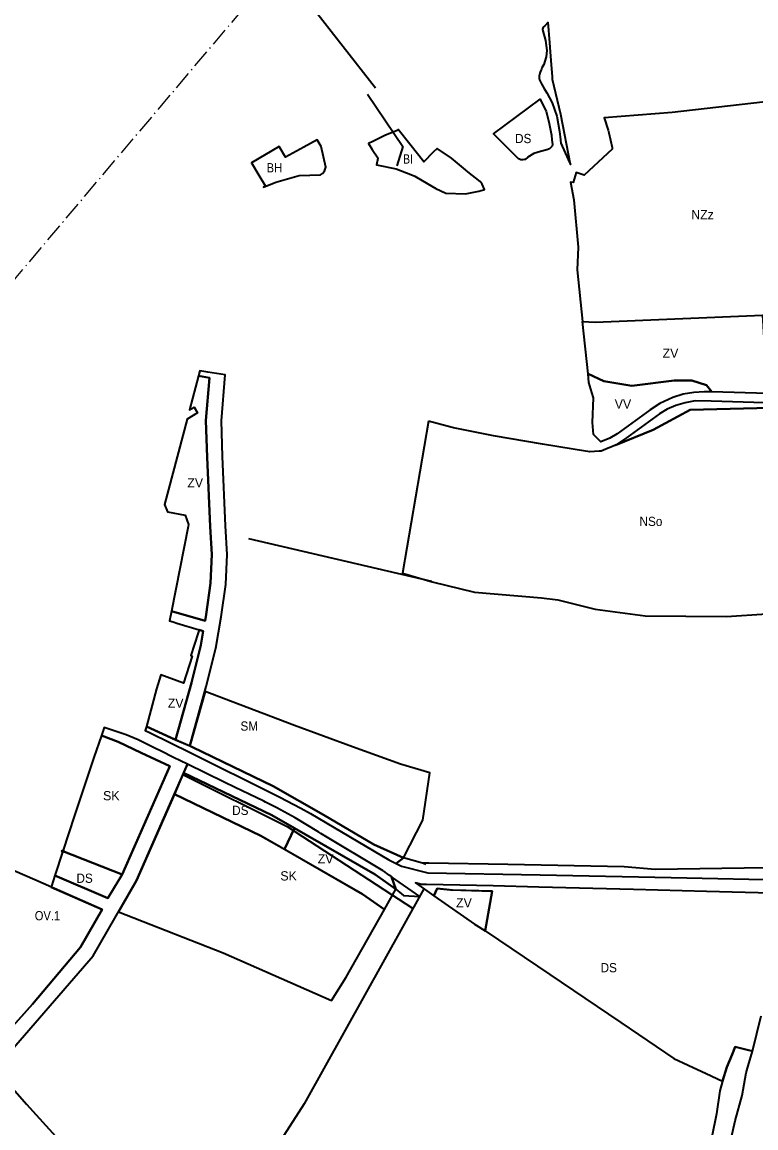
# Model space of a CAD drawing. Extents: x -650276 to -642489, y -1074311 to -1066658.
# Drawn here: x -646170 to -645218, y -1071706 to -1070271 of the extents above; entities that cross this region are included whole.
import ezdxf

# ---------------------------------------------------------------- set-up
doc = ezdxf.new("R2010")
doc.units = 0
doc.header["$LTSCALE"] = 4.8
doc.header["$PDMODE"] = 32
doc.header["$PDSIZE"] = 2.4
doc.linetypes.add('DOT_DASHED', pattern=[7.7, 5, -1.2, 0.3, -1.2])
for name, color, linetype, lineweight in [('1', 7, 'Continuous', 35), ('11', 7, 'Continuous', 35), ('15', 7, 'Continuous', 35), ('18', 7, 'Continuous', 35), ('2', 7, 'Continuous', 35), ('20', 7, 'Continuous', 35), ('24', 7, 'Continuous', 35), ('40', 7, 'Continuous', 35), ('45', 7, 'Continuous', 35), ('46', 7, 'Continuous', 35), ('54', 7, 'Continuous', 35), ('55', 7, 'Continuous', 53), ('56', 7, 'Continuous', 35)]:
    doc.layers.add(name, color=color, linetype=linetype, lineweight=lineweight)
doc.layers.add('62', color=7, linetype='Continuous')
doc.layers.add('63', color=7, linetype='Continuous')

msp = doc.modelspace()

# ---------------------------------------------------------------- linework, layer by layer
at = {"layer": '1'}
msp.add_lwpolyline([(-645862.66, -1070469.5), (-645853.98, -1070483.81), (-645856.87, -1070485.24), (-645840.59, -1070479), (-645810.44, -1070470.17), (-645782.57, -1070469.22), (-645780.38, -1070467.64), (-645777.8, -1070464.4), (-645776.04, -1070459.38), (-645782.13, -1070432.59), (-645786.9, -1070423.81), (-645804.58, -1070433.53), (-645828.24, -1070446.54), (-645836.32, -1070432.55), (-645872.35, -1070453.55)], close=True, dxfattribs=at)
at = {"layer": '11'}
msp.add_lwpolyline([(-646066.165, -1071422.155), (-646153.5, -1071383.85), (-646208.577, -1071360.044), (-646241.68, -1071416.887), (-646258.487, -1071439.265), (-646275.615, -1071460.886), (-646289.976, -1071477.514), (-646330.914, -1071521.11), (-646324, -1071535), (-646217.978, -1071613.552), (-646211.407, -1071606.247), (-646156.471, -1071545.166), (-646094.063, -1071471.007)], close=True, dxfattribs=at)
at = {"layer": '15'}
for points in [[(-645487.361, -1070271.37), (-645491.94, -1070275.85), (-645491.94, -1070275.85), (-645493.8, -1070277.67), (-645494.57, -1070280.34), (-645494.12, -1070282.52), (-645490.79, -1070294.93), (-645489.31, -1070307.77), (-645490.03, -1070316.27), (-645493.05, -1070326.11), (-645495.44, -1070330.67), (-645496.12, -1070332.34), (-645497.83, -1070336.16), (-645498.75, -1070338.98), (-645499.01, -1070340.96), (-645499.09, -1070343.91), (-645498.74, -1070345.87), (-645498, -1070347.74), (-645496.02, -1070351.15), (-645491.97, -1070358.14), (-645488.99, -1070362.96)], [(-645487.361, -1070271.37), (-645491.94, -1070275.85), (-645491.94, -1070275.85), (-645493.8, -1070277.67), (-645494.57, -1070280.34), (-645494.12, -1070282.52), (-645490.79, -1070294.93), (-645489.31, -1070307.77), (-645490.03, -1070316.27), (-645493.05, -1070326.11), (-645495.44, -1070330.67), (-645496.12, -1070332.34), (-645497.83, -1070336.16), (-645498.75, -1070338.98), (-645499.01, -1070340.96), (-645499.09, -1070343.91), (-645498.74, -1070345.87), (-645498, -1070347.74), (-645496.02, -1070351.15), (-645491.97, -1070358.14)], [(-645458.32, -1070455.91), (-645471, -1070391), (-645481.67, -1070345.39), (-645481.65, -1070342.07), (-645483.34, -1070321.17), (-645484.27, -1070309.7), (-645485.21, -1070298.03), (-645487.361, -1070271.37)], [(-645483.34, -1070321.17), (-645484.27, -1070309.7), (-645485.21, -1070298.03), (-645487.361, -1070271.37)], [(-645482.16, -1070375.96), (-645476.12, -1070393.13), (-645472.61, -1070413.13), (-645471.87, -1070419.96), (-645470.99, -1070428.07), (-645461.32, -1070449.31), (-645458.32, -1070455.91), (-645471, -1070391), (-645481.67, -1070345.39), (-645481.65, -1070342.07), (-645483.34, -1070321.17)], [(-645491.97, -1070358.14), (-645488.99, -1070362.96), (-645482.16, -1070375.96)], [(-645488.99, -1070362.96), (-645482.16, -1070375.96), (-645476.12, -1070393.13), (-645472.61, -1070413.13), (-645471.87, -1070419.96), (-645470.99, -1070428.07), (-645461.32, -1070449.31), (-645458.32, -1070455.91)], [(-646197.398, -1071620.579), (-646077.593, -1071482.499), (-646021.674, -1071384.575), (-645964.396, -1071254.314), (-645955.342, -1071233.725), (-645973.324, -1071224.925), (-645989.7, -1071216.91), (-645997.62, -1071213.03), (-646019.41, -1071202.36), (-646035.06, -1071195.87), (-646063.59, -1071186.33), (-646067.097, -1071196.699), (-646045.462, -1071204.917), (-646015.387, -1071218.854), (-645978.403, -1071236.481), (-646040.084, -1071376.813), (-646058.719, -1071407.796), (-646127.301, -1071378.036), (-646131.79, -1071391.83), (-646132.229, -1071393.179), (-646066.165, -1071422.155), (-646094.063, -1071471.007), (-646156.471, -1071545.166), (-646211.407, -1071606.247)], [(-645701.44, -1071372.25), (-645782.32, -1071323.5), (-645784.92, -1071321.93), (-645815.65, -1071303.41), (-645839.37, -1071290.6), (-645854.1, -1071282.93), (-645856.26, -1071281.91), (-645875.48, -1071272.81), (-645893.41, -1071264.04), (-645907.62, -1071257.08), (-645955.342, -1071233.725), (-645960.34, -1071245.09), (-645846, -1071300), (-645712, -1071377), (-645712, -1071377)], [(-645712, -1071377), (-645685.098, -1071395.824), (-645690.677, -1071379.721)]]:
    msp.add_lwpolyline(points, dxfattribs=at)
for points in [[(-645911.345, -1070788.463), (-645906.373, -1070728.716), (-645929.077, -1070725.068), (-645939.27, -1070723.43), (-645940.955, -1070729.799), (-645926.784, -1070732.812), (-645931.369, -1070787.913), (-645930.036, -1070835.367), (-645926.084, -1070925.481), (-645923.919, -1070961.855), (-645925.626, -1070998.754), (-645931.24, -1071039.686), (-645932.635, -1071047.688), (-645976.17, -1071035.39), (-645978.58, -1071047.68), (-645973.77, -1071049.17), (-645968.97, -1071050.66), (-645940.25, -1071059.59), (-645934.978, -1071061.119), (-645938.15, -1071079.311), (-645950.283, -1071128.057), (-645970.966, -1071202.169), (-645952.419, -1071210.117), (-645930.943, -1071133.161), (-645918.57, -1071083.449), (-645911.474, -1071042.764), (-645905.69, -1071000.578), (-645903.891, -1070961.723), (-645906.11, -1070924.449), (-645910.048, -1070834.649)], [(-645694.15, -1071357.83), (-645684.785, -1071362.539), (-645674.947, -1071355.071), (-645713.428, -1071337.765), (-645778.69, -1071299.362), (-645844.079, -1071262.487), (-645948.761, -1071211.885), (-645967, -1071204), (-646008.714, -1071184.746), (-646010.14, -1071190.08), (-646004.65, -1071192.55), (-645951.118, -1071219.11), (-645843.45, -1071272.53), (-645835.76, -1071276.35), (-645808.13, -1071290.78), (-645795.97, -1071297.93), (-645694.15, -1071357.83)]]:
    msp.add_lwpolyline(points, close=True, dxfattribs=at)
msp.add_arc((-645538.107, -1071148.434), 277.076, 233.87926, 236.5888, dxfattribs=at)
at = {"layer": '18'}
for points in [[(-645926.81, -1071141.595), (-645932.502, -1071139.426), (-645952.419, -1071210.117), (-645948.761, -1071211.885)], [(-645678.86, -1071233.58), (-645741.09, -1071211.36), (-645816.47, -1071183.63), (-645926.81, -1071141.595)], [(-645948.761, -1071211.885), (-645844.079, -1071262.487), (-645778.69, -1071299.362), (-645713.428, -1071337.765), (-645674.947, -1071355.071)], [(-645674.947, -1071355.071), (-645650.09, -1071306.433), (-645640.737, -1071244.963), (-645678.86, -1071233.58)]]:
    msp.add_lwpolyline(points, dxfattribs=at)
at = {"layer": '2'}
msp.add_lwpolyline([(-645594.769, -1070494.065), (-645577.47, -1070490.3), (-645571.13, -1070488.89), (-645569.97, -1070488.3), (-645572.86, -1070481.41), (-645575.7, -1070477.77), (-645591.49, -1070465.19), (-645594.62, -1070462.7), (-645612.77, -1070447.82), (-645631.63, -1070435.3), (-645636.42, -1070439.93), (-645648.9, -1070452.38), (-645666.99, -1070429.58), (-645682.02, -1070410.65), (-645683.52, -1070411.71), (-645699.33, -1070418.25), (-645714.74, -1070425.84), (-645720.48, -1070428.75), (-645715.56, -1070436.27), (-645708.28, -1070447.28), (-645708.42, -1070447.94), (-645710.14, -1070456.31), (-645684.78, -1070461.52), (-645665.6, -1070469.04), (-645660.29, -1070471.12), (-645643.4, -1070481.02), (-645633.35, -1070486.91), (-645620.22, -1070493)], close=True, dxfattribs=at)
at = {"layer": '20'}
for points in [[(-645990.48, -1071263.958), (-645978.403, -1071236.481), (-646015.387, -1071218.854), (-646045.462, -1071204.917), (-646067.097, -1071196.699), (-646076.713, -1071225.138)], [(-646076.713, -1071225.138), (-646098.66, -1071290.03), (-646102.011, -1071300.326), (-646117.031, -1071346.48)], [(-646117.031, -1071346.48), (-646040.084, -1071376.813), (-645990.48, -1071263.958)]]:
    msp.add_lwpolyline(points, dxfattribs=at)
msp.add_lwpolyline([(-645699.825, -1071422.134), (-645728.105, -1071402.346), (-645859.986, -1071326.563), (-645972.422, -1071272.568), (-646021.674, -1071384.575), (-646044.948, -1071425.333), (-645909.13, -1071478.56), (-645768.62, -1071540.17), (-645749.631, -1071509.908)], close=True, dxfattribs=at)
msp.add_point((-646117.031, -1071346.48), dxfattribs=at)
at = {"layer": '24'}
for points in [[(-645497.81, -1070370.93), (-645497.81, -1070370.93), (-645490.19, -1070386.97), (-645486.54, -1070400.38), (-645483.29, -1070417.99), (-645482.62, -1070423.93), (-645481.93, -1070430.04), (-645482.18, -1070432.13), (-645485.67, -1070435.7), (-645489.34, -1070437.05), (-645497.33, -1070438.82), (-645505.88, -1070441.74), (-645513.81, -1070446.24), (-645517.44, -1070449.23), (-645517.95, -1070449.45), (-645520.4, -1070449.87), (-645521.41, -1070449.84), (-645522.95, -1070449.61), (-645524.42, -1070449.16), (-645525.75, -1070448.41), (-645527.34, -1070447.1), (-645558.36, -1070416.1)], [(-645829.706, -1071343.963), (-645816.714, -1071316.828), (-645846, -1071300), (-645960.34, -1071245.09), (-645972.422, -1071272.568), (-645859.986, -1071326.563)], [(-646045.393, -1071385.64), (-646040.084, -1071376.813), (-646117.031, -1071346.48), (-646127.301, -1071378.036), (-646058.719, -1071407.796)], [(-645675.177, -1071403.922), (-645675.177, -1071403.922), (-645653.742, -1071405.36), (-645690.677, -1071379.721), (-645685.098, -1071395.824)]]:
    msp.add_lwpolyline(points, close=True, dxfattribs=at)
for points in [[(-645179.18, -1070765.86), (-645275.8, -1070762.66), (-645296.51, -1070762.52), (-645309.78, -1070764.88), (-645321.9, -1070768.47), (-645333.12, -1070773.33), (-645342.94, -1070779.31), (-645385.99, -1070810.35), (-645400.05, -1070819.84), (-645351, -1070800), (-645303, -1070774), (-645182, -1070771)], [(-645176.14, -1071277.26), (-645204.341, -1071368.19), (-645348.55, -1071370.559), (-645388.619, -1071366.991), (-645539.738, -1071364.092), (-645642.431, -1071362.259), (-645650.28, -1071362.07), (-645674.947, -1071355.071), (-645684.785, -1071362.539), (-645677.58, -1071366.16), (-645643.56, -1071374.75), (-645497.84, -1071377.53), (-645327.76, -1071380.76), (-645166.34, -1071384.07)], [(-645164.76, -1071401.79), (-645281.92, -1071398.82), (-645376.87, -1071396.41), (-645499.65, -1071393.3), (-645558.9, -1071391.8), (-645645.368, -1071389.96), (-645651.93, -1071389.82), (-645659.6, -1071387.71), (-645647.727, -1071396.036), (-645635.795, -1071404.403), (-645631.44, -1071394.9), (-645614.201, -1071396.844), (-645560.11, -1071398.7), (-645569.07, -1071449.88), (-645501.37, -1071495.68), (-645393.34, -1071568.75), (-645324.17, -1071615.53), (-645324.17, -1071615.53), (-645305.78, -1071624.13), (-645282.54, -1071634.997), (-645261.094, -1071645.025), (-645255.662, -1071626.67), (-645248.786, -1071610.383), (-645244.81, -1071600.61), (-645222.48, -1071606.08), (-645222.48, -1071606.08), (-645211.27, -1071560.01)], [(-645222.48, -1071606.08), (-645244.81, -1071600.61), (-645248.786, -1071610.383), (-645255.662, -1071626.67)], [(-645222.48, -1071606.08), (-645244.81, -1071600.61), (-645248.786, -1071610.383), (-645255.662, -1071626.67)], [(-645339.904, -1072462.677), (-645347.551, -1072443.527), (-645347.677, -1072391.355), (-645346.62, -1072330.914), (-645343.458, -1072278.998), (-645339.908, -1072235.158), (-645335.367, -1072185.207), (-645325.498, -1072102.789), (-645309.01, -1071998.147), (-645285.617, -1071875.733), (-645244.798, -1071696.585), (-645235.793, -1071663.703), (-645230.436, -1071634.261), (-645227.905, -1071625.277), (-645222.48, -1071606.08)], [(-645339.904, -1072462.677), (-645347.551, -1072443.527), (-645347.677, -1072391.355), (-645346.62, -1072330.914), (-645343.458, -1072278.998), (-645339.908, -1072235.158), (-645335.367, -1072185.207), (-645325.498, -1072102.789), (-645309.01, -1071998.147), (-645285.617, -1071875.733), (-645244.798, -1071696.585), (-645235.793, -1071663.703), (-645230.436, -1071634.261), (-645227.905, -1071625.277), (-645222.48, -1071606.08)], [(-645255.662, -1071626.67), (-645261.094, -1071645.025), (-645264.841, -1071657.687), (-645269.077, -1071687.396), (-645274.868, -1071717.176), (-645286.175, -1071761.228), (-645300.076, -1071820.179), (-645313.153, -1071883.081), (-645326.343, -1071952.807)], [(-645255.662, -1071626.67), (-645261.094, -1071645.025), (-645264.841, -1071657.687), (-645269.077, -1071687.396), (-645274.868, -1071717.176), (-645286.175, -1071761.228), (-645300.076, -1071820.179), (-645313.153, -1071883.081)]]:
    msp.add_lwpolyline(points, dxfattribs=at)
at = {"layer": '40'}
for points in [[(-645442.836, -1070659.455), (-645426.34, -1070660.33), (-645209.41, -1070651.2), (-645206.7, -1070694.76), (-645204.66, -1070718.51), (-645203.13, -1070749.36), (-645202.96, -1070752.89), (-645275.236, -1070750.954), (-645282, -1070742), (-645301, -1070736), (-645324, -1070736), (-645379, -1070743), (-645415, -1070737), (-645435.711, -1070727.497)], [(-645932.635, -1071047.688), (-645931.24, -1071039.686), (-645925.626, -1070998.754), (-645923.919, -1070961.855), (-645926.084, -1070925.481), (-645930.036, -1070835.367), (-645931.369, -1070787.913), (-645926.784, -1070732.812), (-645940.955, -1070729.799), (-645952.65, -1070773.98), (-645946.81, -1070770.47), (-645942.3, -1070777.96), (-645955.86, -1070786.21), (-645980.01, -1070877.28), (-645985.28, -1070897.13), (-645981.48, -1070906.35), (-645958.21, -1070910.84), (-645954.01, -1070922.8), (-645954.492, -1070925.251), (-645976.17, -1071035.39)], [(-645970.966, -1071202.169), (-645950.283, -1071128.057), (-645938.15, -1071079.311), (-645934.978, -1071061.119), (-645940.25, -1071059.59), (-645941.45, -1071063.3), (-645950.96, -1071092.8), (-645949.21, -1071093.62), (-645960.66, -1071128.71), (-645990.14, -1071117.76), (-645995.74, -1071136.22), (-646008.714, -1071184.746)], [(-645712, -1071377), (-645816.714, -1071316.828), (-645829.706, -1071343.963), (-645728.105, -1071402.346), (-645699.825, -1071422.134), (-645685.098, -1071395.824)], [(-645583.18, -1071441.3), (-645580.947, -1071442.658), (-645569.07, -1071449.88), (-645560.11, -1071398.7), (-645611.58, -1071397.14), (-645631.44, -1071394.9), (-645635.795, -1071404.403)]]:
    msp.add_lwpolyline(points, close=True, dxfattribs=at)
at = {"layer": '45'}
msp.add_lwpolyline([(-645275.236, -1070750.954), (-645285.11, -1070750.69), (-645298.41, -1070751.48), (-645312.2, -1070753.77), (-645325.82, -1070757.94), (-645342.41, -1070765.76), (-645354.98, -1070774.28), (-645398.04, -1070805.44), (-645407.37, -1070810.95), (-645419.18, -1070815.44), (-645424.969, -1070809.563), (-645428.39, -1070806.09), (-645430, -1070790.68), (-645428.73, -1070758.67), (-645430.84, -1070751.43), (-645434.53, -1070738.77), (-645435.711, -1070727.497), (-645415, -1070737), (-645379, -1070743), (-645324, -1070736), (-645301, -1070736), (-645282, -1070742)], close=True, dxfattribs=at)
at = {"layer": '46'}
for points in [[(-645023.048, -1070595.033), (-645014.277, -1070543.11), (-645004.327, -1070461.264), (-645001.312, -1070412.099), (-645003.03, -1070365.427), (-645003.102, -1070365.432), (-645006.86, -1070365.38), (-645179.26, -1070371.74), (-645326.62, -1070388.32), (-645414.65, -1070395.37), (-645409.38, -1070411.41), (-645408.66, -1070414.62), (-645404.34, -1070433.93), (-645404.4, -1070435.88), (-645440.61, -1070469.53), (-645451.226, -1070466.394), (-645455.09, -1070479.21), (-645458.46, -1070478.86), (-645454.02, -1070501.52), (-645448.36, -1070563), (-645449.82, -1070592.72), (-645442.834, -1070659.455)], [(-645442.834, -1070659.455), (-645426.34, -1070660.33), (-645209.41, -1070651.2)]]:
    msp.add_lwpolyline(points, dxfattribs=at)
at = {"layer": '54'}
for p, q in [((-645875.986, -1070940.86), (-645638.682, -1070996.266)), ((-645650.559, -1071361.544), (-645646.066, -1071363.608))]:
    msp.add_line(p, q, dxfattribs=at)
for points in [[(-645903.547, -1070057.381), (-645879.191, -1070130.665), (-645848.973, -1070180.543), (-645834.684, -1070241.324), (-645795.429, -1070249.201), (-645711.259, -1070356.569)], [(-645721.753, -1070364.565), (-645675.805, -1070432.543), (-645683.821, -1070457.746)], [(-645961.323, -1071247.326), (-645825.908, -1071314.509), (-645661.944, -1071421.517)], [(-645648.577, -1071395.44), (-645803.784, -1071674.386), (-645877, -1071788), (-645965, -1071892)], [(-646336.784, -1071524.232), (-646218.737, -1071612.767), (-646164.374, -1071674.897), (-645904.456, -1071961.331), (-645718.199, -1072151.712), (-645526.944, -1072343.922), (-645538, -1072384), (-645459, -1072440), (-645389, -1072483), (-645335, -1072526), (-645287, -1072569), (-645227, -1072617), (-645139.573, -1072694.628), (-645084.365, -1072788.086)]]:
    msp.add_lwpolyline(points, dxfattribs=at)
at = {"layer": '55', "linetype": 'DOT_DASHED', "lineweight": 25}
msp.add_line((-646590, -1071090), (-645744.292, -1070089.84), dxfattribs=at)
at = {"layer": '56'}
for points in [[(-645100.268, -1070771.946), (-645143, -1070770), (-645161, -1070770), (-645182, -1070771), (-645303, -1070774), (-645351, -1070800), (-645400.05, -1070819.84), (-645406.09, -1070822.34), (-645409.52, -1070823.76), (-645418.67, -1070827.72), (-645421.09, -1070827.89), (-645433.49, -1070828.76), (-645452.31, -1070825.52), (-645455.184, -1070825.042)], [(-645642.52, -1070788.7), (-645676.292, -1070985.89), (-645637.94, -1070997.4), (-645583.18, -1071010.7), (-645495.87, -1071017.81)], [(-645455.184, -1070825.042), (-645494.82, -1070818.45), (-645558.3, -1070808), (-645610.25, -1070797.55), (-645625, -1070793.5), (-645642.52, -1070788.7)], [(-645495.87, -1071017.81), (-645475.01, -1071020.72), (-645426.38, -1071032.8), (-645361.54, -1071041.54), (-645255.93, -1071042.36), (-645203.66, -1071038.81), (-645193.24, -1071037.31), (-645186.18, -1071030.83), (-645180.72, -1071028.86), (-645178.73, -1070972.35), (-645167.47, -1070975.2), (-645134.973, -1070977.077), (-645134.973, -1070977.077), (-645130.749, -1070959.561)]]:
    msp.add_lwpolyline(points, dxfattribs=at)

# ---------------------------------------------------------------- texts
at = {"layer": '62'}
for s, width, p in [('DS', 0.95, (-645530.386, -1070428.148)), ('BH', 0.9, (-645852.646, -1070466.101)), ('SM', 0.95, (-645886.606, -1071190.345)), ('DS', 0.95, (-645897.407, -1071299.717)), ('DS', 0.95, (-646099.407, -1071387.717)), ('OV.1', 0.9, (-646153.486, -1071436.306)), ('DS', 0.95, (-645419.407, -1071503.717))]:
    msp.add_text(s, height=12, dxfattribs=dict(at, width=width)).set_placement(p)
for s, p in [('ZV', (-645955.588, -1070874.768)), ('ZV', (-645980.931, -1071160.591)), ('SK', (-646064.883, -1071280.659)), ('ZV', (-645786.398, -1071362.507)), ('SK', (-645834.883, -1071384.659)), ('ZV', (-645606.931, -1071419.591))]:
    msp.add_text(s, height=12, dxfattribs=at).set_placement(p)
at = {"layer": '63'}
for s, width, p in [('BI', 0.85, (-645675.657, -1070454.713)), ('NSo', 0.95, (-645368.866, -1070924.823))]:
    msp.add_text(s, height=12, dxfattribs=dict(at, width=width)).set_placement(p)
for s, p in [('NZz', (-645301.866, -1070526.823)), ('ZV', (-645338.931, -1070706.591)), ('VV', (-645401.075, -1070772.614))]:
    msp.add_text(s, height=12, dxfattribs=at).set_placement(p)

doc.saveas('drawing.dxf')
